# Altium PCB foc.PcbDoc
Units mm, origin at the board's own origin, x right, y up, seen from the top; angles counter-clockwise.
Board outline 89.54 x 51.18 mm, 2 copper layers (Top Layer, Bottom Layer); 143 components, 82 nets, 471 pads, 233 vias.
Unrouted connection lines stored in the file: 246.
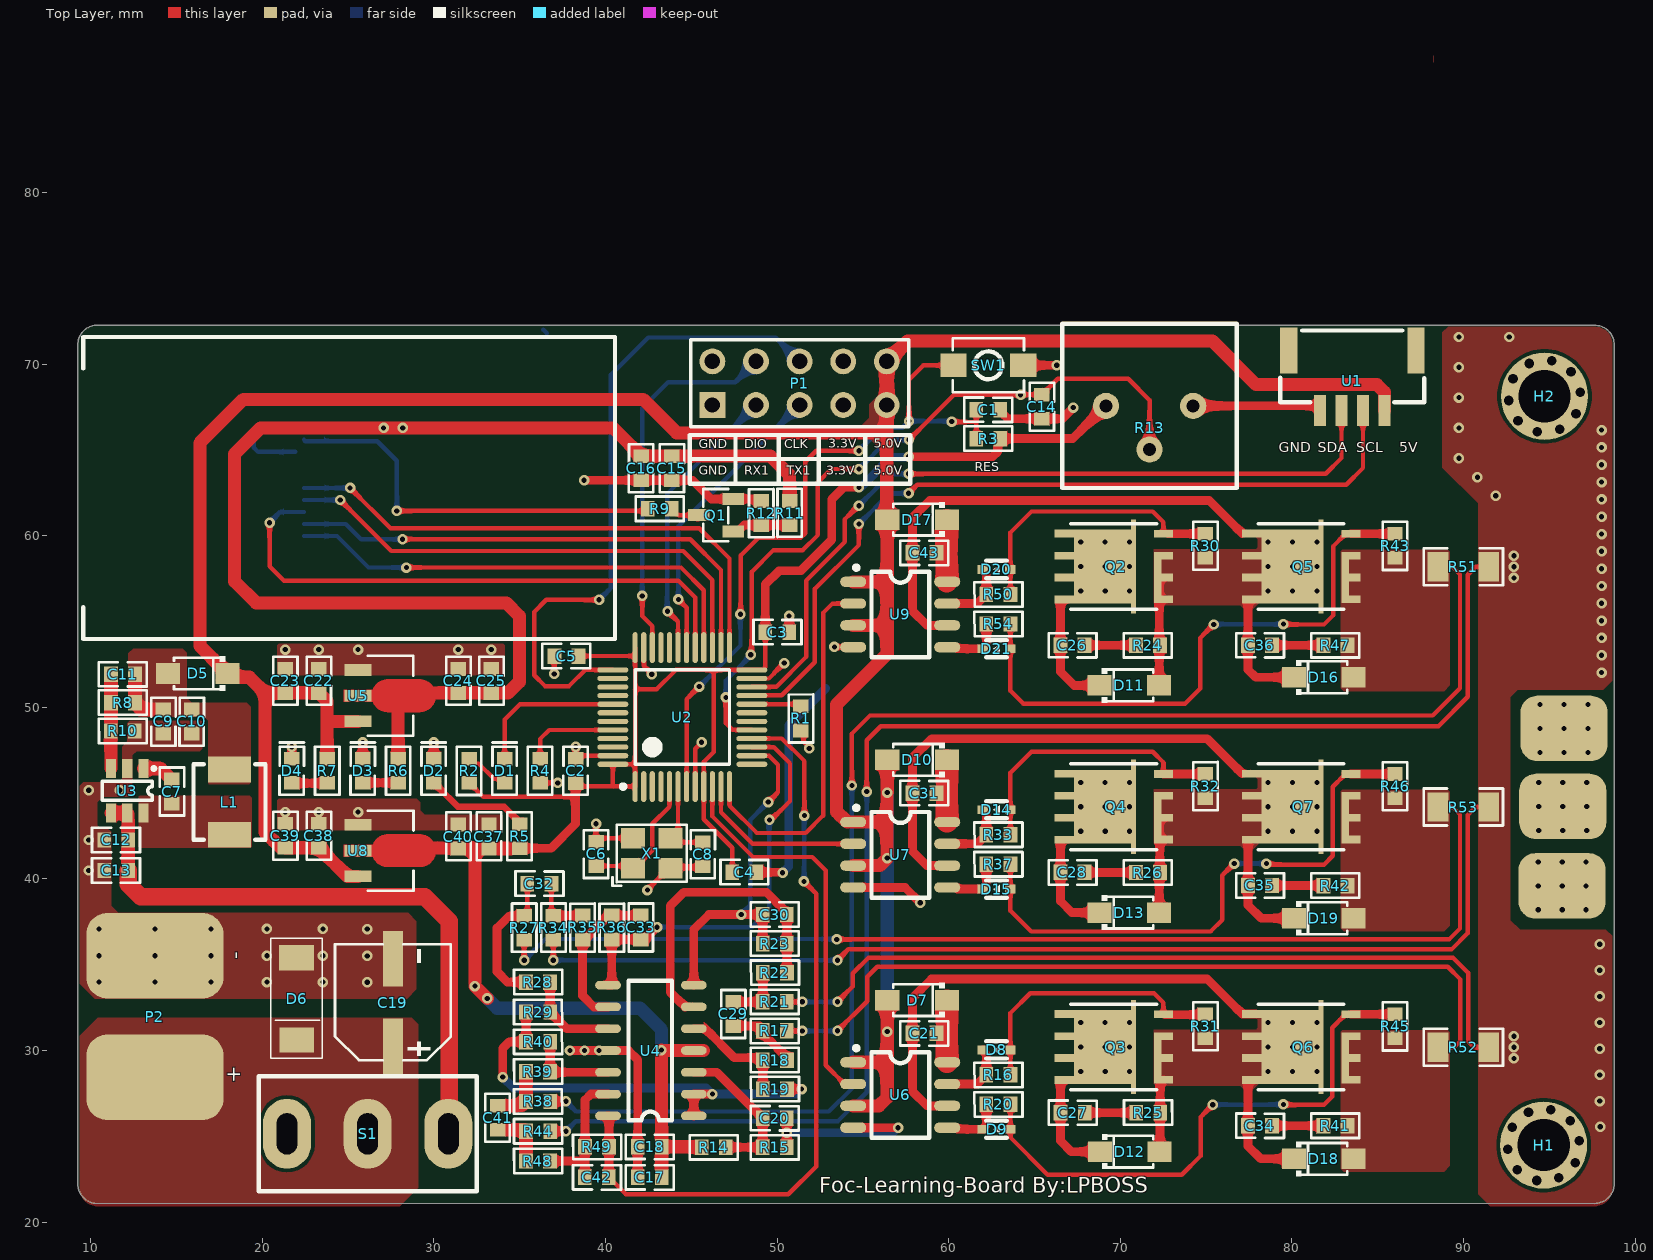
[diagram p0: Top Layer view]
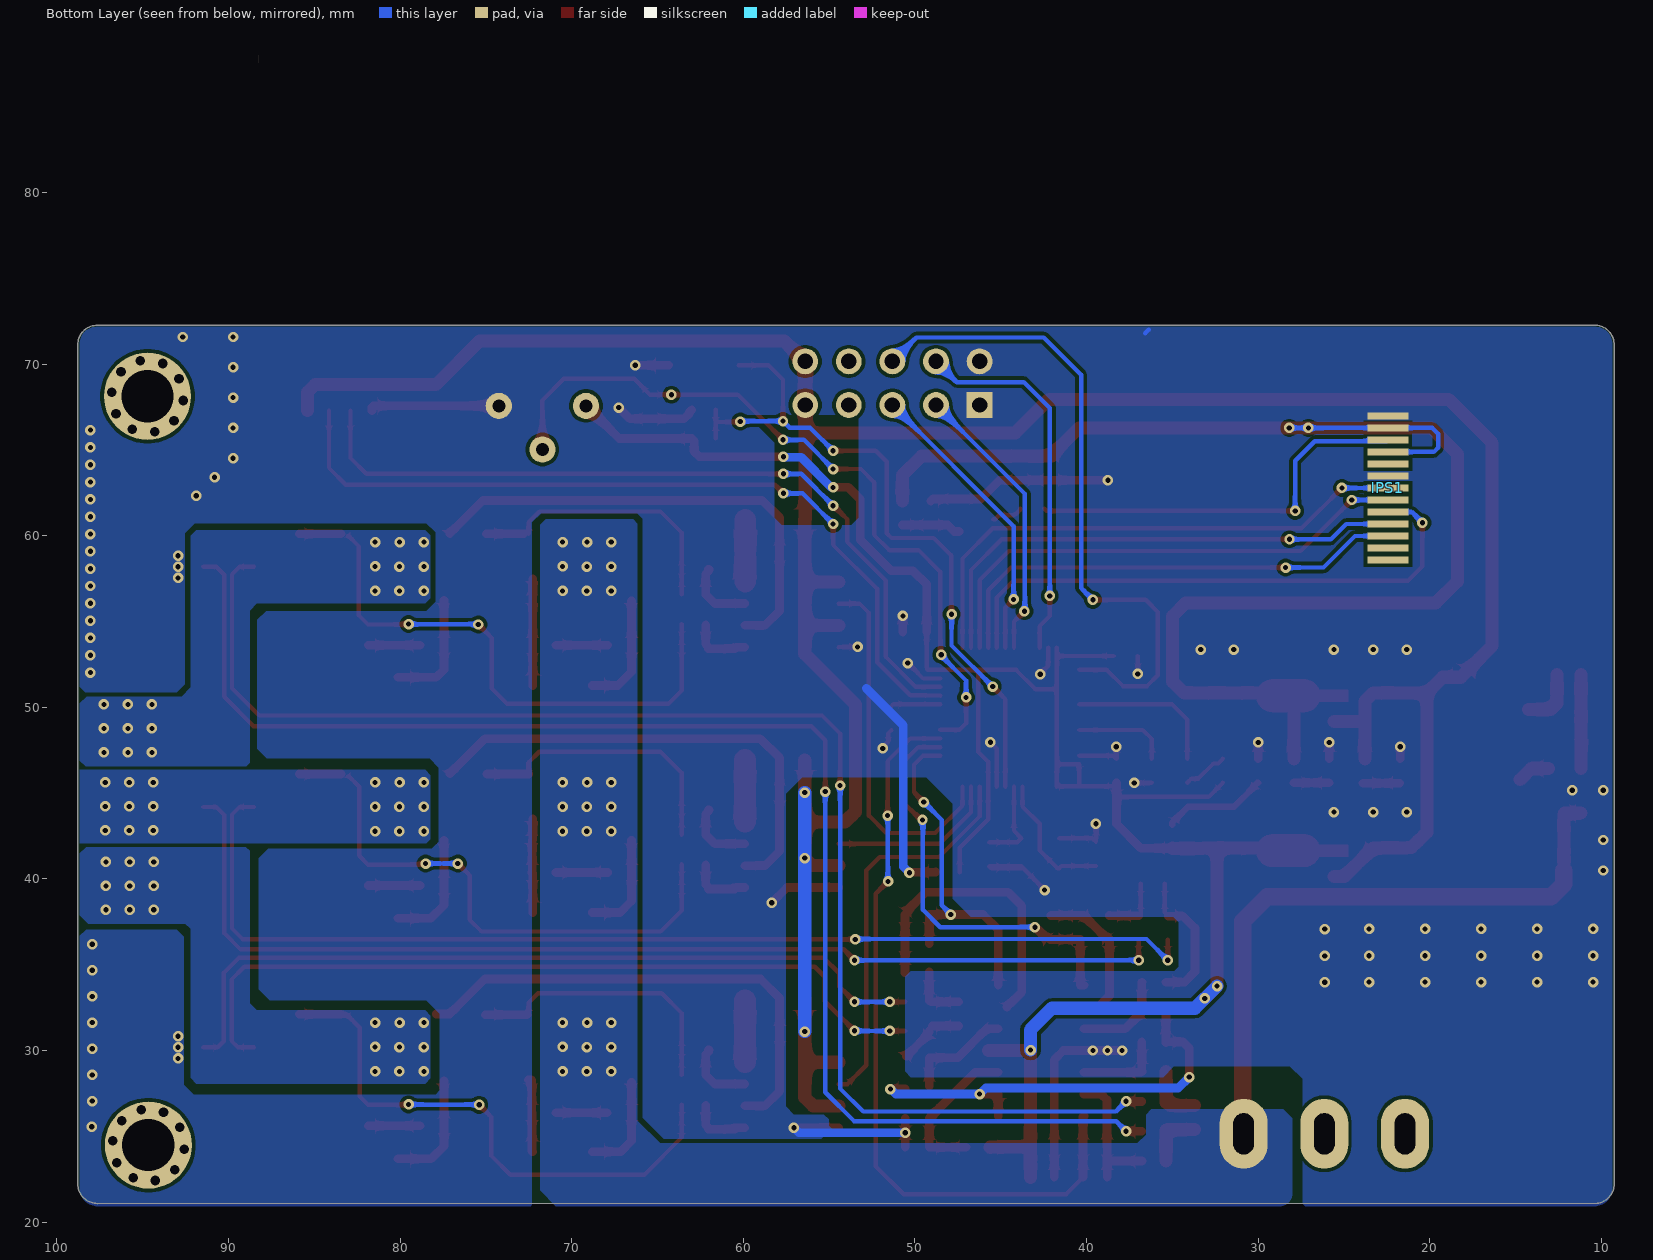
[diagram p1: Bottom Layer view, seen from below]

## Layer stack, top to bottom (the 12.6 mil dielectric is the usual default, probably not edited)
Top Solder: solder mask 0.0102, Solder Resist, Dk 3.5
Top Layer: signal copper 0.0356
Dielectric 1: dielectric 0.32, FR-4, Dk 4.8
Bottom Layer: signal copper 0.0356
Bottom Solder: solder mask 0.0102, Solder Resist, Dk 3.5

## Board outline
10.239,21.092 cw(c10.39,22.226) 9.245,22.226 9.245,22.227 9.245,71.102 9.244,71.12 cw(c10.389,71.12) 10.389,72.265 10.406,72.263 97.635,72.263 97.636,72.263 cw(c97.636,71.119) 98.781,71.12 98.781,71.119 98.781,22.228 98.781,22.226 cw(c97.636,22.226) 97.636,21.082

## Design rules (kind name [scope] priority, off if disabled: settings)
Clearance [All] p1: gap=0.203 ignorepadtopadclearanceinfootprint=TRUE
ComponentClearance [All] p1: gap=0 collisioncheckmode=3 verticalgap=0 showdistances=FALSE
PlaneConnect [All] p1: planeconnectstyle=Direct reliefexpansion=0.508 reliefentries=4 reliefconductorwidth=0.254 reliefairgap=0.254
PolygonConnect [All] p1: connectstyle=Direct reliefconductorwidth=0.254 reliefentries=4 polygonreliefangle="90 Angle" airgapwidth=0.254
RoutingVias [All] p1: holewidth=0.711 width=1.27 viastyle="Through Hole" minholewidth=0.025 minwidth=0.025 maxholewidth=0.711 maxwidth=1.27
SolderMaskExpansion [All] p1: expansion=0.102 istentingtop=FALSE
Width [All] p1: maxlimit=2.54 minlimit=0.025 preferedwidth=0.254
28 further rules are at their usual default settings.

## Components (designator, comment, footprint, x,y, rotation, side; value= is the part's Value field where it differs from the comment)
C1 "104" C0603 62.306,67.335 r0 top
C2 "104" C0603 38.252,46.289 r270 top
C3 "104" C0603 50.013,54.381 r180 top
C4 "104" C0603 48.087,40.395 r180 top
C5 "104" C0603 37.719,52.984 r0 top
C6 "20P" C0603 39.446,41.453 r90 top
C7 "104" C0603 14.732,45.085 r270 top
C8 "20P" C0603 45.665,41.433 r270 top
C9 "22UF" C0603 14.238,49.171 r90 top
C10 "104" C0603 15.889,49.171 r90 top
C11 "220pf" C0603 11.877,51.919 r0 top
C12 "104" C0603 11.481,42.266 r0 top
C13 "22uf" C0603 11.481,40.488 r0 top
C14 "104" C0603 65.43,67.513 r90 top
C15 "10uf" C0603 43.866,63.935 r90 top
C16 "104" C0603 42.078,63.935 r90 top
C17 "10uF" C0603 42.569,22.608 r180 top
C18 "104" C0603 42.569,24.383 r180 top
C19 "470uf" CAP-SMD_BD6.3-L6.6-W6.6-LS7.2-R-RD 27.61,32.791 r270 top
C20 "104" C0603 49.86,26.055 r180 top
C21 "104" C0603 58.582,30.995 r0 top
C22 "10uf" C0603 23.292,51.536 r270 top
C23 "104" C0603 21.336,51.536 r270 top
C24 "10uf" C0603 31.42,51.536 r270 top
C25 "104" C0603 33.351,51.536 r270 top
C26 "104" C0603 67.208,53.614 r180 top
C27 "104" C0603 67.219,26.376 r180 top
C28 "104" C0603 67.208,40.376 r180 top
C29 "104" C0603 47.447,32.131 r90 top
C30 "104" C0603 49.86,37.922 r0 top
C31 "1uf" C0603 58.582,44.995 r0 top
C32 "104" C0603 36.144,39.726 r180 top
C33 "104" C0603 42.062,37.173 r90 top
C34 "104" C0603 78.133,25.614 r180 top
C35 "104" C0603 78.133,39.614 r180 top
C36 "104" C0603 78.133,53.614 r180 top
C37 "104" C0603 33.208,42.468 r270 top
C38 "104" C0603 23.297,42.507 r270 top
C39 "10uf" C0603 21.342,42.507 r270 top
C40 "10uf" C0603 31.425,42.468 r270 top
C41 "104" C0603 33.706,26.086 r90 top
C42 "104" C0603 39.494,22.608 r180 top
C43 "104" C0603 58.582,58.995 r0 top
D1 "LED" LED0603 34.123,46.304 r90 top
D2 "LED" LED0603 29.987,46.304 r90 top
D3 "LED" LED0603 25.852,46.304 r90 top
D4 "LED" LED0603 21.717,46.304 r90 top
D5 "Diode" SOD-123FL_L2.7-W1.8-LS3.8-RD 16.231,51.968 r180 top
D6 "TVS-7.4/12V" SMA 22.996,36.145 r270 top
D7 "Diode" SOD-123FL_L2.7-W1.8-LS3.8-RD 58.152,32.933 r180 top
D8 "Diode" ESC_L1.2-W0.8-LS1.6-RD 62.778,30.029 r0 top
D9 "Diode" ESC_L1.2-W0.8-LS1.6-RD 62.788,25.407 r0 top
D10 "Diode" SOD-123FL_L2.7-W1.8-LS3.8-RD 58.152,46.933 r180 top
D11 "Diode" SOD-123FL_L2.7-W1.8-LS3.8-RD 70.53,51.272 r0 top
D12 "Diode" SOD-123FL_L2.7-W1.8-LS3.8-RD 70.541,24.105 r0 top
D13 "Diode" SOD-123FL_L2.7-W1.8-LS3.8-RD 70.53,38.034 r0 top
D14 "Diode" ESC_L1.2-W0.8-LS1.6-RD 62.778,44.029 r0 top
D15 "Diode" ESC_L1.2-W0.8-LS1.6-RD 62.778,39.407 r0 top
D16 "Diode" SOD-123FL_L2.7-W1.8-LS3.8-RD 81.849,51.745 r0 top
D17 "Diode" SOD-123FL_L2.7-W1.8-LS3.8-RD 58.152,60.933 r180 top
D18 "Diode" SOD-123FL_L2.7-W1.8-LS3.8-RD 81.849,23.683 r0 top
D19 "Diode" SOD-123FL_L2.7-W1.8-LS3.8-RD 81.849,37.704 r0 top
D20 "Diode" ESC_L1.2-W0.8-LS1.6-RD 62.778,58.029 r0 top
D21 "Diode" ESC_L1.2-W0.8-LS1.6-RD 62.778,53.407 r0 top
H1 "Hole" 铜柱孔3 94.666,24.486 r0 top
H2 "Hole" 铜柱孔3 94.717,68.123 r0 top
IPS1 "IPS1.14" IPS 15.661,62.781 r0 top locked
L1 "3.3uH" "0402 TPC 4*4*2" 18.085,44.475 r270 top
P1 "Header 5X2" HDR2X5 46.228,67.615 r0 top
P2 "电源" POWER 13.741,31.979 r90 top
Q1 "44H11" SOT-23-3_L2.9-W1.3-P1.90-LS2.4-BR 46.431,61.19 r0 top
Q2 "N-MOS" TDSON-8 69.609,58.201 r90 top
Q3 "N-MOS" TDSON-8 69.609,30.201 r90 top
Q4 "N-MOS" TDSON-8 69.609,44.201 r90 top
Q5 "N-MOS" TDSON-8 80.534,58.201 r90 top
Q6 "N-MOS" TDSON-8 80.534,30.201 r90 top
Q7 "N-MOS" TDSON-8 80.534,44.201 r90 top
R1 "10K" R0603 51.384,49.352 r90 top
R2 "10K" R0603 32.05,46.296 r90 top
R3 "10K" R0603 62.298,65.659 r180 top
R4 "10K" R0603 36.185,46.296 r270 top
R5 "10K" R0603 34.996,42.483 r90 top
R6 "10K" R0603 27.914,46.296 r270 top
R7 "10K" R0603 23.779,46.296 r270 top
R8 "73.2K" R0603 11.877,50.265 r0 top
R9 "24R" R0603 43.154,61.57 r180 top
R10 "10K" R0603 11.869,48.617 r180 top
R11 "1k" R0603 50.728,61.32 r270 top
R12 "10k" R0603 49.077,61.32 r90 top
R13 "WH160-1-503(B50K)" 滑动变阻器 71.704,66.294 r0 top
R14 "5.1K" R0603 46.304,24.359 r180 top
R15 "5.1K" R0603 49.86,24.359 r180 top
R16 "10" R0603 62.892,28.573 r180 top
R17 "1K" R0603 49.86,31.138 r0 top
R18 "1K" R0603 49.869,29.442 r0 top
R19 "15K" R0603 49.869,27.751 r180 top
R20 "10" R0603 62.892,26.854 r180 top
R21 "1K" R0603 49.86,32.834 r0 top
R22 "1K" R0603 49.869,34.535 r180 top
R23 "15K" R0603 49.86,36.226 r0 top
R24 "10" R0603 71.608,53.608 r0 top
R25 "10" R0603 71.619,26.376 r0 top
R26 "10" R0603 71.608,40.37 r0 top
R27 "1K" R0603 35.259,37.157 r270 top
R28 "1K" R0603 36.062,33.984 r180 top
R29 "15K" R0603 36.071,32.24 r0 top
R30 "10K" R0603 74.957,59.411 r90 top
R31 "10K" R0603 74.957,31.411 r90 top
R32 "10K" R0603 74.957,45.411 r90 top
R33 "10" R0603 62.892,42.573 r180 top
R34 "1K" R0603 36.958,37.157 r270 top
R35 "1K" R0603 38.663,37.166 r90 top
R36 "15K" R0603 40.363,37.166 r90 top
R37 "10" R0603 62.892,40.854 r180 top
R38 "1K" R0603 36.071,27.027 r0 top
R39 "1K" R0603 36.062,28.77 r180 top
R40 "15K" R0603 36.071,30.503 r0 top
R41 "10" R0603 82.533,25.608 r0 top
R42 "10" R0603 82.533,39.608 r0 top
R43 "10K" R0603 86.006,59.406 r90 top
R44 "1K" R0603 36.071,25.29 r0 top
R45 "10K" R0603 86.006,31.406 r90 top
R46 "10K" R0603 86.006,45.406 r90 top
R47 "10" R0603 82.533,53.608 r0 top
R48 "1K" R0603 36.062,23.557 r180 top
R49 "15K" R0603 39.501,24.383 r180 top
R50 "10" R0603 62.892,56.573 r180 top
R51 "20mR" R1206 89.989,58.186 r180 top
R52 "20mR" R1206 89.989,30.186 r180 top
R53 "20mR" R1206 89.989,44.186 r180 top
R54 "10" R0603 62.892,54.854 r180 top
S1 "MTS-10x" SW-TH_HOOYA_SS-12D10G4 26.137,25.146 r180 top
SW1 "Switch" SW-SMD_L4.0-W2.9-LS5.0 62.306,69.926 r180 top
U1 "GH125-4P" CONN-SMD_4P-P1.27_GH125-S04DCA-00 83.515,69.037 r180 top
U2 "STM32F103C8T6" 48P 44.475,49.428 r90 top
U3 "RY8121" SOT-23-6 12.127,45.131 r270 top
U4 "MCP6024" SOP14_L 42.647,29.997 r180 top
U5 "AMS1117" SOT-89_L4.5-W2.5-P1.50-LS4.2-BR 26.932,50.672 r180 top
U6 "EG2104" SOP-8 57.172,27.407 r270 top
U7 "EG2104" SOP-8 57.172,41.407 r270 top
U8 "AMS1117" SOT-89_L4.5-W2.5-P1.50-LS4.2-BR 26.938,41.643 r180 top
U9 "EG2104" SOP-8 57.172,55.407 r270 top
X1 "XTAL-4" OSC-SMD_4P-L3.2-W2.5-BL 42.693,41.498 r0 top

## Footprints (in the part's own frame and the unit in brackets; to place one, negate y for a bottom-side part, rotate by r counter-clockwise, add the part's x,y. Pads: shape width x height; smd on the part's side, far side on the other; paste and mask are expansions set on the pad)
48P [mm] "stm32f103"
  oval 1.8x0.3 smd: 1(-4.05,2.75) 2(-4.05,2.25) 3(-4.05,1.75) 4(-4.05,1.25) 5(-4.05,0.75) 6(-4.05,0.25) 7(-4.05,-0.25) 8(-4.05,-0.75) 9(-4.05,-1.25) 10(-4.05,-1.75) 11(-4.05,-2.25) 12(-4.05,-2.75) 25(4.05,-2.75) 26(4.05,-2.25) 27(4.05,-1.75) 28(4.05,-1.25) 29(4.05,-0.75) 30(4.05,-0.25) 31(4.05,0.25) 32(4.05,0.75) 33(4.05,1.25) 34(4.05,1.75) 35(4.05,2.25) 36(4.05,2.75)
  oval 0.3x1.8 smd: 13(-2.75,-4.05) 14(-2.25,-4.05) 15(-1.75,-4.05) 16(-1.25,-4.05) 17(-0.75,-4.05) 18(-0.25,-4.05) 19(0.25,-4.05) 20(0.75,-4.05) 21(1.25,-4.05) 22(1.75,-4.05) 23(2.25,-4.05) 24(2.75,-4.05) 37(2.75,4.05) 38(2.25,4.05) 39(1.75,4.05) 40(1.25,4.05) 41(0.75,4.05) 42(0.25,4.05) 43(-0.25,4.05) 44(-0.75,4.05) 45(-1.25,4.05) 46(-1.75,4.05) 47(-2.25,4.05) 48(-2.75,4.05)
  silkscreen extent -4.17,-2.75 2.75,3.57
"0402 TPC 4*4*2" [mm] "4.2mm x 4.4mm x 2mm 一体成型功率电感"
  rect 1.5x2.5 smd: 1(-1.9,0) 2(1.9,0)
  silkscreen extent -2.2,-2.1 2.2,2.1
C0603 [mm]
  rect 0.8x0.9 smd mask+0.051: 1(-0.7,0) 2(0.7,0)
  silkscreen extent -1.41,-0.71 1.39,0.72
CAP-SMD_BD6.3-L6.6-W6.6-LS7.2-R-RD [mm]
  rect 3.26x1.15 smd mask+0.051: 1(2.555,0) 2(-2.555,0)
  silkscreen extent -3.39,-3.38 3.36,3.38
CONN-SMD_4P-P1.27_GH125-S04DCA-00 [mm] "P4"
  rect 0.7x1.8 smd mask+0.05: 1(-1.875,1.75) 2(-0.625,1.75) 3(0.625,1.75) 4(1.875,1.75)
  rect 1x2.7 smd mask+0.05: 5(3.705,-1.75) 6(-3.705,-1.75)
  silkscreen extent -4.19,-2.92 4.19,1.27
ESC_L1.2-W0.8-LS1.6-RD [mil]
  rect 23.6x19.7 smd mask+2: 1(-31.5,0) 2(31.5,0)
  silkscreen extent -24,-20 24,20
HDR2X5 [mm] "Connector; Header; 5x2 Position"
  rect 1.5x1.5 hole 0.9: 1(0,0)
  round 1.5 hole 0.9: 2(0,2.54) 3(2.54,0) 4(2.54,2.54) 5(5.08,0) 6(5.08,2.54) 7(7.62,0) 8(7.62,2.54) 9(10.16,0) 10(10.16,2.54)
  silkscreen extent -1.27,-1.27 11.43,3.81
IPS [mm]
  rect 2.4x0.4 smd far side: 1(6.767,-4.2) 2(6.767,-3.5) 3(6.767,-2.8) 4(6.767,-2.1) 5(6.767,-1.4) 6(6.767,-0.7) 7(6.767,0) 8(6.767,0.7) 9(6.767,1.4) 10(6.767,2.1) 11(6.767,2.8) 12(6.767,3.5) 13(6.767,4.2)
  silkscreen extent -6.11,-8.8 24.89,8.8
LED0603 [mm]
  rect 0.8x0.9 smd mask+0.051: A(-0.7,0) N(0.7,0)
  silkscreen extent -1.41,-0.71 1.64,0.72
OSC-SMD_4P-L3.2-W2.5-BL [mm] "贴片晶振"
  rect 1.4x1.2 smd: 1(-1.1,-0.875) 2(1.1,-0.875) 3(1.1,0.875) 4(-1.1,0.875)
  silkscreen extent -2.29,-1.9 2.03,1.65
POWER [mm]
  rrect50% 5x8 smd: 1(-3.541,-0.001) 2(3.541,0.001)
R0603 [mm]
  rect 0.8x0.9 smd mask+0.051: 1(-0.7,0) 2(0.7,0)
  silkscreen extent -1.41,-0.71 1.4,0.72
R1206 [mm]
  rect 1.208x1.701 smd paste-100 mask+0.051: 1(-1.479,0) 2(1.479,0)
  silkscreen extent -2.31,-1.08 2.31,1.08
SMA [mm]
  rect 1.47x2.02 smd: A(0.74,-1.01) N(5.53,-1)
  silkscreen extent -0.4,-2.5 6.6,0.5
SOD-123FL_L2.7-W1.8-LS3.8-RD [mm]
  rect 1.4x1.2 smd: 1(-1.735,0) 2(1.735,0)
  silkscreen extent -1.6,-1 1.38,1
SOP14_L [mm] "8.7*6.2*1.8mm（长宽高）"
  oval 1.5x0.5 smd: 1(-2.5,3.81) 2(-2.5,2.54) 3(-2.5,1.27) 4(-2.5,0) 5(-2.5,-1.27) 6(-2.5,-2.54) 7(-2.5,-3.81) 8(2.5,-3.81) 9(2.5,-2.54) 10(2.5,-1.27) 11(2.5,0) 12(2.5,1.27) 13(2.5,2.54) 14(2.5,3.81)
  silkscreen extent -1.23,-4.06 1.31,4.06
SOP-8 [mm]
  oval 0.6x1.52 smd mask+0.051: 1(-1.905,-2.74) 2(-0.635,-2.74) 3(0.635,-2.74) 4(1.905,-2.74) 5(1.905,2.74) 6(0.635,2.74) 7(-0.635,2.74) 8(-1.905,2.74)
  silkscreen extent -2.85,-2.68 2.5,1.7
SOT-23-3_L2.9-W1.3-P1.90-LS2.4-BR [mm]
  rect 1.25x0.7 smd mask+0.051: 1(1,-0.95) 2(1,0.95) 3(-1,0)
  silkscreen extent -0.73,-1.53 0.73,1.53
SOT-23-6 [mm] "SOT23, 6-Leads, Body 2.90x2.80mm, Pitch 0.95mm, IPC Medium Density"
  rect 1.1x0.6 smd: 1(-1.3,0.95) 2(-1.3,0) 3(-1.3,-0.95) 4(1.3,-0.95) 5(1.3,0) 6(1.3,0.95)
  silkscreen extent -1.37,-1.45 0.55,1.63
SOT-89_L4.5-W2.5-P1.50-LS4.2-BR [mm]
  rect 1.575x0.672 smd paste+0 mask+0.051: 1(1.356,-1.5) 2(1.356,0) 3(1.356,1.5)
  Top Layer region: -2.233,0.95 -0.378,0.95 -0.334,0.949 -0.289,0.946 -0.245,0.94 -0.201,0.933 -0.158,0.924 -0.115,0.912 -0.072,0.899 -0.03,0.884 0.011,0.866 0.051,0.847 0.09,0.826 0.128,0.803 0.166,0.779 0.201,0.752 0.236,0.724 0.269,0.695 0.301,0.664 0.332,0.631 0.36,0.597 0.388,0.562 0.413,0.525 0.437,0.488 0.459,0.449 0.479,0.409 0.491,0.356 2.195,0.356 2.195,-0.356 0.491,-0.356 0.479,-0.41 0.459,-0.449 0.437,-0.488 0.413,-0.526 0.388,-0.562 0.36,-0.598 0.332,-0.631 0.301,-0.664 0.269,-0.695 0.236,-0.725 0.201,-0.753 0.166,-0.779 0.128,-0.804 0.09,-0.827 0.051,-0.848 0.011,-0.867 -0.03,-0.884 -0.072,-0.9 -0.115,-0.913 -0.158,-0.924 -0.201,-0.934 -0.245,-0.941 -0.289,-0.946 -0.334,-0.949 -0.378,-0.95 -2.233,-0.95 -2.277,-0.949 -2.321,-0.946 -2.366,-0.941 -2.41,-0.934 -2.453,-0.924 -2.496,-0.913 -2.539,-0.9 -2.581,-0.884 -2.622,-0.867 -2.662,-0.848 -2.701,-0.827 -2.739,-0.804 -2.776,-0.779 -2.812,-0.753 -2.847,-0.725 -2.88,-0.695 -2.912,-0.664 -2.942,-0.631 -2.971,-0.598 -2.998,-0.562 -3.024,-0.526 -3.048,-0.488 -3.07,-0.449 -3.09,-0.41 -3.108,-0.369 -3.124,-0.327 -3.139,-0.285 -3.151,-0.243 -3.161,-0.199 -3.17,-0.155 -3.176,-0.111 -3.18,-0.067 -3.182,-0.023 -3.182,0.022 -3.18,0.067 -3.176,0.111 -3.17,0.155 -3.161,0.199 -3.151,0.242 -3.139,0.285 -3.124,0.327 -3.108,0.368 -3.09,0.409 -3.07,0.449 -3.048,0.488 -3.024,0.525 -2.998,0.562 -2.971,0.597 -2.942,0.631 -2.912,0.664 -2.88,0.695 -2.847,0.724 -2.812,0.752 -2.776,0.779 -2.739,0.803 -2.701,0.826 -2.662,0.847 -2.622,0.866 -2.581,0.884 -2.539,0.899 -2.496,0.912 -2.453,0.924 -2.41,0.933 -2.366,0.94 -2.321,0.946 -2.277,0.949
  silkscreen extent -1.87,-2.33 0.78,2.33
SW-SMD_L4.0-W2.9-LS5.0 [mm]
  rect 1.53x1.36 smd mask+0.051: 1(-2.035,0) 2(2.035,0)
  silkscreen extent -2.08,-1.58 2.08,1.58
SW-TH_HOOYA_SS-12D10G4 [mil] "拨动开关"
  oval 110x160 hole 47.24 slot 94.49 at 90 deg: 1(-185.04,0) 2(0,0) 3(185.04,0)
  silkscreen extent -250,-132 250,132
TDSON-8 [mm]
  rect 0.45x1.6 smd: 1(-1.925,2.65) 1(-0.635,2.65) 1(0.635,2.65) 1(1.925,2.65)
  rect 5.5x0.3 smd: 1(0,-1.158)
  rect 4.3x3.605 smd: 1(0,0.495)
  rect 0.45x1.1 smd: 2(1.905,-2.9) 3(-1.905,-2.9) 3(-0.635,-2.9) 3(0.635,-2.9)
  rect 2.99x0.45 smd: 3(-0.635,-2.575)
  silkscreen extent -2.5,-2.5 2.5,2.5
滑动变阻器 [mil]
  round 60 hole 30: 1(-100,50) 2(0,-50) 3(100,50)
  silkscreen extent -200,-139 200,239
铜柱孔3 [mil]
  round 23 hole 22: 11(-82.21,-9.67) 11(-72.19,40.5) 11(-60.83,-56.14) 11(-34.6,75.2) 11(-16.21,-81.17) 11(16.21,81.17) 11(34.6,-75.2) 11(60.83,56.14) 11(72.19,-40.5) 11(82.21,9.67)
  round 200 hole 120: 11(0,0)

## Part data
C1 C2 C3 C4 C5 C6 C7 C8 C9 C10 C11 C12 C13 C14 C15 C16 C17 C18 C20 C21 C22 C23 C24 C25 C26 C27 C28 C29 C30 C31 C32 C33 C34 C35 C36 C37 C38 C39 C40 C41 C42 C43: library part C, "无极性电容"
C19: library part CAP+, "电解电容 10uf  贴片型 钽电容的正极是实物有线的一段", BOM_JLCPCB Part Class="Extended Part", BOM_Manufacturer=ROQANG, BOM_Manufacturer Part=RVT1V100M0405
D5 D7 D8 D9 D10 D11 D12 D13 D14 D15 D16 D17 D18 D19 D20 D21: library part 二极管, "Diode 1N series"
H1 H2: "电机的洞"
L1: library part L, "电感"
P1: "Header, 5-Pin, Dual row"
P2: library part power
Q1: library part NPN, "NPN型"
Q2 Q3 Q4 Q5 Q6 Q7: "N沟场效应管"
R1 R2 R3 R4 R5 R6 R7 R8 R9 R10 R11 R12 R14 R15 R16 R17 R18 R19 R20 R21 R22 R23 R24 R25 R26 R27 R28 R29 R30 R31 R32 R33 R34 R35 R36 R37 R38 R39 R40 R41 R42 R43 R44 R45 R46 R47 R48 R49 R50 R51 R52 R53 R54: library part R, "电阻"
R13: "拨码开关", Manufacturer=JML
S1: "MTS10x系列3脚扭子开关"
SW1: "SWITCH"
U3: "18V 2A 1MHz Synchronous Step-Down Regulator"
X1: "贴片晶振"

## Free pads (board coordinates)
  rrect50% 5.08x3.81 smd mask+0.051: 7(95.746,39.591) 7(95.783,44.221) 7(95.86,48.768)

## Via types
v1: diameter 0.61, hole 0.305, Top Layer to Bottom Layer, tented both sides, 233 vias

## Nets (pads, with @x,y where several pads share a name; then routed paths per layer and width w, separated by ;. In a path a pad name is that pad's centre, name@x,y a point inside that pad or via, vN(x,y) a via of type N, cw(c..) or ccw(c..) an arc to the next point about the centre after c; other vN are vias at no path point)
1.65V: R19.1 R29.1 R40.1 U4.1 U4.2 | length 26.1
  Top Layer w0.508: v1(34.011,28.448) 34.011,30.124 34.389,30.503 R40.1 ; R40.1@35.371,30.453 R29.1 ; U4.1 U4.2 v1(46.228,27.457) ; R19.1 v1(51.424,27.751)
  Bottom Layer w0.508: v1(34.011,28.448) 34.646,27.813 45.872,27.813 46.22,27.465 46.22,27.457 51.103,27.457 51.396,27.751 v1(51.424,27.751)
3.3V: C2.2 C3.2 C4.2 C5.2 C17.1 C18.1 C37.2 C40.2 R2.1 R3.1 R5.1 R13.1 R14.2 U2.1 U2.9 U2.24 U2.36 U2.48 U4.4 U8.2 | length 122.5
  Top Layer w0.254: R2.1 32.865,44.78 38.252,44.78 ; C2.2@38.252,45.63 38.492,45.39 40.488,45.39 ; C5.2 U2.36@41.725,52.984 ; U2.1 U2.1@41.725,45.39 ; U2.36 U2.36@41.725,52.984 ; C4.2 47.387,41.818 45.725,43.479 U2.9 45.725,46.818 46.304,47.396 46.304,52.178 ; C3.2 49.313,52.35 49.284,52.322 49.284,52.2 49.263,52.178 46.304,52.178 ; 40.488,45.39 40.425,45.452 U2.48 41.725,46.678 ; 40.488,45.39 U2.1@41.725,45.39 ; U2.1@41.725,45.39 41.725,46.678 ; 41.725,46.678 41.725,51.054 ; 41.725,51.054 U2.36@41.725,52.984 ; 41.725,51.054 42.977,51.054 44.101,52.178 46.304,52.178
  Top Layer w0.508: R5.1 36.83,41.783 38.252,43.205 38.252,44.78 38.252,45.39 C2.2 ; C3.2 49.313,57.161 50.114,57.963 51.384,57.963 53.188,59.766 53.188,62.128 53.873,62.814 v1(54.762,62.814) ; v1(57.658,64.601) 62.554,64.601 62.852,64.898 62.852,65.513 R3.1 63.195,65.659 67.229,65.659 69.134,67.564 R13.1
  Top Layer w0.762: 28.88,41.783 28.904,41.807 31.425,41.807 32.391,41.807 ; v1(33.112,33.03) v1(32.391,33.751) 32.391,41.807 ; C37.2@33.185,41.807 32.391,41.807 ; C37.2 34.981,41.768 R5.1 ; v1(43.256,30.023) v1@43.269,30.01 ; C17.1 C18.1 ; R14.2 45.579,24.383 C18.1 ; U4.4@45.695,29.997 43.282,29.997 v1@43.269,30.01 ; C18.1 v1@43.269,30.01
  Bottom Layer w0.508: v1(54.762,62.814) 54.782,62.834 54.895,62.834 56.629,64.567 57.552,64.567 57.567,64.581 57.644,64.581 v1@57.658,64.567
  Bottom Layer w0.762: v1(32.391,33.751) 33.68,32.461 42.012,32.461 43.269,31.204 43.269,30.036 v1(43.256,30.023)
3.3V_ips: C15.2 C16.2 C24.2 C25.2 IPS1.10 IPS1.12 R6.1 R11.1 U5.2 | length 86.8
  Top Layer w0.762: R6.1 27.914,50.317 28.219,50.622 ; 28.778,50.648 28.967,50.836 C24.2 C25.2 34.326,50.836 34.976,51.486 34.976,55.321 34.214,56.083 19.634,56.083 18.39,57.328 18.39,64.77 19.9,66.281 v1(27.064,66.281) v1(28.182,66.281) 40.433,66.281 42.009,64.704 42.009,64.654 42.028,64.635 C15.2 49.614,64.635 50.728,63.521 R11.1
  Bottom Layer w0.254: IPS1.10@21.92,64.881 19.752,64.881 19.507,65.126 19.507,65.938 19.849,66.281 IPS1.12 v1(27.064,66.281) v1(28.182,66.281)
5V: C22.2 C23.2 C38.2 C39.2 D5.1 D7.2 D10.2 D17.2 P1.9 P1.10 R7.1 U1.1 U5.3 U6.1 U6.3 U7.1 U7.3 U8.3 U9.1 U9.3 | length 180.4
  Top Layer w0.762: R7.1 23.779,49.154 ; 23.798,49.172 23.779,49.154 ; 23.825,49.172 U5.3 ; U8.3 24.961,40.143 C38.2 C39.2 21.323,41.826 21.07,41.826 20.673,42.223 20.65,42.223 20.165,42.707 20.165,50.825 ; U6.3 55.931,26.772 56.417,27.258 56.417,29.312 ; U6.1 56.417,29.312 ; U7.3 55.978,40.772 v1@56.415,41.209 ; U9.3 56.417,54.772 ; U9.1 56.417,57.312 ; D17.2@56.388,60.962 56.388,65.989 ; v1(56.413,41.211) 56.413,43.312 ; v1(56.413,45.026) 56.413,43.312 ; D7.2@56.417,33.029 D7.2 v1(56.417,31.1) 56.417,29.312 ; v1@56.417,45.026 D10.2 ; D17.2 56.417,57.312 ; U1.1 85.39,68.362 84.944,68.809 77.902,68.809 75.362,71.349 57.61,71.349 56.416,70.155 P1.10 P1.9 56.388,65.989 ; 20.165,50.825 22.035,50.825 22.046,50.836 C22.2 23.779,50.349 23.779,49.154 ; 20.165,50.825 19.241,51.749 18.185,51.749 16.358,53.576 16.358,65.405 18.898,67.945 42.189,67.945 44.145,65.989 56.388,65.989 ; 56.413,43.312 U7.1 54.066,43.312 53.467,43.91 53.467,50.165 56.417,53.115 56.417,54.772 ; 56.417,54.772 56.417,57.312
  Bottom Layer w0.762: v1(56.417,31.1) 56.417,32.933 v1@56.417,45.026
12V: C12.2 C13.2 C26.2 C27.2 C28.2 D11.1 D12.1 D13.1 Q2.1 Q3.1 Q4.1 S1.1 U3.4 U3.5 | length 55.9
  Top Layer w0.508: Q3.1@66.508,28.154 66.508,26.386 C27.2 66.508,26.365 66.508,24.741 67.145,24.105 D12.1 ; Q4.1@66.508,42.247 C28.2 66.508,38.711 67.185,38.034 D13.1 ; Q2.1@66.508,56.195 C26.2 66.508,52.072 67.307,51.272 D11.1
  Top Layer w0.762: U3.4 U3.5 ; C13.2 C12.2 U3.5@12.181,43.778
  Top Layer w1.016: C13.2 12.181,39.686 12.903,38.964 29.464,38.964 30.886,37.541 30.886,25.196 S1.1
  other v1: 67.686,28.778 69.113,28.778 70.531,28.778 67.686,30.196 69.109,30.201 70.531,30.205 67.686,31.623 69.104,31.623 70.531,31.623 67.686,42.778 69.113,42.778 70.531,42.778 67.686,44.196 69.109,44.201 70.531,44.205 67.686,45.623 69.104,45.623 70.531,45.623 67.686,56.778 69.113,56.778 70.531,56.778 67.686,58.196 69.109,58.201 70.531,58.205 67.686,59.623 69.104,59.623 70.531,59.623
A: C21.1 C34.2 D12.2 D18.1 pad.7@95.746,39.591 Q3.3 Q6.1 R25.2 R31.1 U6.6 | length 40.3
  Top Layer w0.508: U6.6 58.737,26.772 57.882,27.627 C21.1 57.882,33.049 58.996,34.163 75.069,34.163 77.107,32.126 Q6.1@77.884,32.126 ; D12.2 72.308,24.137 72.308,26.365 R25.2 72.319,28.267 72.348,28.296 Q3.3@72.509,28.296 ; Q6.1@77.433,28.23 77.433,24.433 78.183,23.683 D18.1
  other v1: 78.611,28.778 80.038,28.778 81.456,28.778 78.611,30.196 80.034,30.201 81.456,30.205 78.611,31.623 80.029,31.623 81.456,31.623 94.349,38.194 95.746,38.194 97.143,38.194 94.349,39.591 95.746,39.591 97.143,39.591 94.349,40.988 95.746,40.988 97.143,40.988
B: C31.1 C35.2 D13.2 D19.1 pad.7@95.783,44.221 Q4.3 Q7.1 R26.2 R32.1 U7.6 | length 40.6
  Top Layer w0.508: U7.6 58.737,40.772 57.882,41.627 C31.1 57.882,47.049 59.006,48.173 75.059,48.173 Q7.1@77.107,46.126 ; D13.2 72.265,40.327 R26.2 72.294,40.384 72.294,42.267 72.265,42.296 Q4.3@72.265,43.484 ; Q7.1@77.433,42.23 C35.2 77.433,38.48 78.209,37.704 D19.1
  other v1: 78.611,42.778 80.038,42.778 81.456,42.778 94.386,42.824 95.783,42.824 97.18,42.824 78.611,44.196 80.034,44.201 81.456,44.205 94.386,44.221 95.783,44.221 97.18,44.221 78.611,45.623 80.029,45.623 81.456,45.623 94.386,45.618 95.783,45.618 97.18,45.618
BOOT0: R4.1 U2.44 | length 5.6
  Top Layer w0.254: R4.1 36.185,48.148 36.715,48.678 U2.44
BOOT1: R1.2 U2.20 | length 2.9
  Top Layer w0.254: U2.20 51.258,50.178 R1.2
C: C36.2 C43.1 D11.2 D16.1 pad.7@95.86,48.768 Q2.3 Q5.1 R24.2 R30.1 U9.6 | length 41.4
  Top Layer w0.508: U9.6 58.737,54.772 57.882,55.627 C43.1 57.882,61.049 58.885,62.052 75.18,62.052 Q5.1@77.107,60.126 ; D11.2 Q2.3@72.265,57.484 ; Q5.1@77.433,56.23 77.433,52.196 77.883,51.745 D16.1
  other v1: 94.463,47.371 95.86,47.371 97.257,47.371 94.463,48.768 95.86,48.768 97.257,48.768 94.463,50.165 95.86,50.165 97.257,50.165 78.611,56.778 80.038,56.778 81.456,56.778 78.611,58.196 80.034,58.201 81.456,58.205 78.611,59.623 80.029,59.623 81.456,59.623
DC: IPS1.5 U2.29 | length 33.3
  Top Layer w0.254: v1(20.422,60.757) 20.422,58.217 21.26,57.379 44.247,57.379 45.225,56.4 U2.29
  Bottom Layer w0.254: v1(20.422,60.757) 21.045,61.381 IPS1.5
GND: C1.2 C2.1 C3.1 C4.1 C5.1 C6.2 C8.2 C9.1 C10.1 C12.1 C13.1 C14.1 C15.1 C16.1 C17.2 C18.2 C19.2 C20.1 C22.1 C23.1 C24.1 C25.1 C37.1 C38.1 C39.1 C40.1 D2.N D3.N D4.N D6.A IPS1.8 IPS1.13 P1.1 P1.2 P2.2 Q1.2 R1.1 R4.2 R10.1 R12.2 R13.3 R15.1 R21.2 R34.2 R44.2 R51.1 R52.1 R53.1 SW1.1 U1.4 U2.8 U2.23 U2.35 U2.47 U3.2 U4.11 U5.1 U6.4 U7.4 U8.1 U9.4 X1.2 X1.4 | length 286.6
  Top Layer w0.254: R4.2 36.188,45.593 v1(37.211,45.593) ; v1(36.957,35.255) R34.2 ; v1(37.008,51.943) 37.008,52.973 C5.1 ; C2.1 C2.1@38.258,46.994 ; v1(38.258,47.694) C2.1@38.258,46.994 ; v1(39.446,43.205) C6.2 39.666,42.373 X1.4 ; U2.47 38.442,47.178 C2.1@38.258,46.994 ; U2.35 42.234,53.47 42.234,52.424 42.697,51.961 v1(42.697,51.918) ; v1(42.443,39.345) 42.443,39.373 43.803,40.733 C8.2 45.556,40.623 X1.2 ; U2.8 45.225,47.588 v1(45.593,47.955) ; U2.23 49.519,51.678 v1(50.419,52.578) ; R21.2 v1(51.46,32.834) ; R1.1 51.543,48.494 51.543,48.02 51.867,47.696 v1(51.867,47.6) ; v1(53.34,53.518) 53.348,53.51 54.424,53.51 U9.4 ; v1(53.518,32.842) 54.407,33.731 54.407,34.493 55.321,35.408 89.383,35.408 90.272,34.519 90.272,30.531 90.617,30.186 R52.1 ; v1(53.518,35.264) 54.144,35.89 55.605,35.89 89.298,35.89 90.248,36.84 90.248,43.724 90.71,44.186 R53.1 ; v1(55.22,45.085) 55.22,48.082 56.032,48.895 88.536,48.895 90.248,50.607 90.248,57.724 90.71,58.186 R51.1
  Top Layer w0.508: D4.N v1(21.717,47.694) ; D3.N v1(25.852,47.948) ; D2.N v1(29.988,47.948) ; R44.2 37.685,25.29 v1(37.694,25.298) ; v1(36.957,35.255) v1(36.957,35.255) ; v1@37.922,29.972 37.95,29.972 37.975,29.997 41.337,29.997 41.869,29.465 C18.2 C17.2 ; v1(38.749,63.235) C16.1 45.071,63.235 46.165,62.14 48.956,62.14 R12.2 ; C4.1 48.804,40.378 50.3,40.378 v1(50.317,40.361) ; R15.1 v1(50.56,25.207) C20.1 ; v1(50.698,55.321) 50.706,55.314 50.706,54.389 C3.1 ; U6.4 v1(57.048,25.502) ; U7.4 57.45,39.502 v1(58.344,38.608) ; C1.2 63.152,67.189 63.152,67.111 63.45,66.813 C14.1 66.61,66.813 v1(67.259,67.462) ; SW1.1 v1(66.294,69.926) ; R13.3 81.544,67.564 81.64,67.468 U1.4
  Bottom Layer w0.254: 36.373,72.009 36.576,71.806 ; v1(36.957,35.255) v1@53.518,35.255 ; v1(37.694,25.298) 38.278,25.883 53.543,25.883 55.22,27.559 v1(55.22,45.085) ; v1(51.46,32.834) v1@53.518,32.834
  Bottom Layer w0.508: v1(50.317,40.361) 50.673,40.716 50.673,48.946 52.831,51.104 ; v1(50.56,25.207) 56.753,25.207 v1(57.048,25.502)
  other v1: 97.968,25.552 97.942,27.051 97.942,28.575 92.939,29.538 37.922,29.997 38.773,29.997 39.624,29.997 97.942,30.099 92.939,30.186 92.939,30.833 97.942,31.623 97.942,33.147 10.476,33.985 13.74,33.985 17.004,33.985 20.269,33.985 23.533,33.985 26.111,33.975 97.942,34.671 10.476,35.519 13.74,35.519 17.004,35.519 20.269,35.519 23.533,35.519 26.111,35.509 97.942,36.195 10.476,37.084 13.74,37.084 17.004,37.084 20.269,37.084 23.533,37.084 26.111,37.074 9.881,40.488 9.881,42.266 21.336,43.891 23.292,43.891 25.581,43.891 9.881,45.161 11.684,45.161 98.044,52.019 98.044,53.029 21.331,53.365 23.287,53.365 25.576,53.365 31.415,53.365 33.345,53.365 98.044,54.038 98.044,55.048 98.044,56.057 98.044,57.067 92.939,57.538 98.044,58.076 92.939,58.186 92.939,58.833 98.044,59.085 98.044,60.095 98.044,61.104 98.044,62.114 91.882,62.321 98.044,63.123 90.805,63.398 98.044,64.133 89.728,64.516 98.044,65.142 98.044,66.152 89.728,66.281 89.728,68.047 89.728,69.812 89.728,71.577 92.669,71.577
HO_A: D8.2 Q3.2 R16.1 R31.2 | length 16.4
  Top Layer w0.254: R16.1 63.592,30.029 63.592,32.181 64.747,33.335 71.96,33.335 72.509,32.787 Q3.2
  Top Layer w0.508: Q3.2@72.585,32.085 R31.2@75.028,32.085
HO_B: D14.2 Q4.2 R32.2 R33.1 | length 16.4
  Top Layer w0.254: R33.1 63.592,46.181 64.823,47.411 71.884,47.411 72.509,46.787 Q4.2 ; R32.2@74.952,46.106 R32.2
  Top Layer w0.508: Q4.2 R32.2@74.952,46.106
HO_C: D20.2 Q2.2 R30.2 R50.1 | length 16.1
  Top Layer w0.254: R50.1 63.592,58.029 63.592,60.181 64.823,61.411 71.884,61.411 72.509,60.787 Q2.2
  Top Layer w0.508: Q2.2@72.805,60.111 R30.2
IA+: D18.2 Q6.3 R17.2 R41.2 R45.1 R52.2 | length 47
  Top Layer w0.254: R17.2 v1(51.46,31.138) ; v1(53.518,31.146) 55.245,32.873 55.245,34.29 55.829,34.874 89.078,34.874 89.814,34.138 89.814,30.556 89.444,30.186 R52.2
  Bottom Layer w0.254: v1(51.46,31.138) v1@53.518,31.138
IB+: D19.2 Q7.3 R27.2 R42.2 R46.1 R53.2 | length 64.6
  Top Layer w0.254: v1(35.257,35.255) v1(35.257,35.255) R27.2 ; v1(53.467,36.474) 89.159,36.474 89.791,37.106 89.791,43.749 89.355,44.186 R53.2
  Bottom Layer w0.254: v1(35.257,35.255) 36.502,36.5 53.442,36.5 v1(53.467,36.474)
IC+: D16.2 Q5.3 R38.2 R43.1 R47.2 R51.2 | length 83.7
  Top Layer w0.254: v1(54.356,45.441) 54.356,48.463 55.412,49.52 88.205,49.52 89.791,51.106 89.791,57.749 89.355,58.186 R51.2
  Top Layer w0.508: R38.2 37.685,27.027 v1(37.694,27.036)
  Bottom Layer w0.254: v1(37.694,27.036) 38.288,26.441 53.01,26.441 54.356,27.788 v1(54.356,45.441)
INA+: C20.2 R14.1 R15.2 U4.3 | length 9
  Top Layer w0.508: U4.3 46.488,28.727 C20.2 R15.2 R14.1
INB+: R18.1 R19.2 U4.5 | length 6.4
  Top Layer w0.508: U4.5 45.822,31.267 47.507,29.582 49.169,29.582 R19.2@49.169,27.92
INB-: C30.2 R22.1 R23.2 U4.6 | length 17.1
  Top Layer w0.508: U4.6@44.651,32.537 44.628,32.537 43.764,33.401 43.764,38.43 44.552,39.218 49.378,39.218 C30.2@50.444,38.151 ; C30.2 50.569,37.914 R22.1
INC+: R28.1 R29.2 U4.10 | length 5.6
  Top Layer w0.508: R28.1 36.771,33.975 36.771,32.19 36.917,32.044 36.967,32.044 37.744,31.267 U4.10
INC-: C33.2 R35.1 R36.2 U4.9 | length 9
  Top Layer w0.508: R35.1 38.663,33.193 39.319,32.537 U4.9 ; R35.1@38.711,36.418 40.16,37.866 R36.2 42.055,37.866 C33.2 ; C33.2@42.055,37.853 C33.2@42.062,37.86
IND+: R39.1 R40.2 U4.12 | length 5.1
  Top Layer w0.508: R40.2 36.771,28.779 R39.1 36.805,28.727 U4.12
IND-: C42.2 R48.1 R49.2 U4.13 | length 8.1
  Top Layer w0.254: 38.728,23.557 38.794,23.492
  Top Layer w0.508: R48.1 38.728,23.557 ; C42.2 38.794,23.492 38.794,24.376 R49.2 38.8,27.116 39.141,27.457 U4.13
LED_PWM: D1.N U2.41 | length 9
  Top Layer w0.254: D1.N 34.123,49.286 35.015,50.178 U2.41
LO_A: D9.2 Q6.2 R20.1 R45.2 | length 32.7
  Top Layer w0.254: R20.1 63.592,25.407 63.594,25.405 63.594,24.925 65.761,22.758 73.584,22.758 74.678,23.853 74.678,26.122 v1(75.389,26.833) ; v1(79.504,26.858) 79.529,26.833 81.866,26.833 82.349,27.315 82.349,31.329 83.011,31.991 83.011,32.008 83.109,32.106 Q6.2
  Top Layer w0.508: Q6.2 R45.2@85.882,32.106
  Bottom Layer w0.254: v1(75.389,26.833) 75.402,26.845 79.491,26.845 v1(79.504,26.858)
LO_B: D15.2 Q7.2 R37.1 R46.2 | length 32.8
  Top Layer w0.254: R37.1 63.592,39.407 63.592,38.147 64.808,36.932 75.26,36.932 75.946,37.617 75.946,40.208 v1(76.632,40.894) ; v1(78.511,40.894) 78.577,40.828 81.866,40.828 82.384,41.346 82.384,45.363 Q7.2@83.011,45.991
  Top Layer w0.508: Q7.2 R46.2@85.882,46.106
  Bottom Layer w0.254: v1(76.632,40.894) v1(78.511,40.894)
LO_C: D21.2 Q5.2 R43.2 R54.1 | length 34.2
  Top Layer w0.254: R54.1 63.592,53.407 63.592,50.958 64.349,50.201 73.764,50.201 74.653,51.09 74.653,54.036 v1(75.44,54.824) ; v1(79.504,54.849) 79.529,54.824 81.866,54.824 82.396,55.354 82.396,59.376 Q5.2@83.011,59.991
  Top Layer w0.508: Q5.2 R43.2@85.882,60.106
  Bottom Layer w0.254: v1(75.44,54.824) 75.453,54.836 79.491,54.836 v1(79.504,54.849)
NetC7_1: C7.1 U3.1 | length 1.9
  Top Layer w0.762: U3.1 14.086,46.431 C7.1
NetC7_2: C7.2 L1.2 U3.6
NetC9_2: C9.2 C10.2 C11.2 D5.2 L1.1 R8.2 | length 3.5
  Top Layer w0.762: R8.2@12.577,50.215 C11.2 ; R8.2@12.596,50.196 12.922,49.871 C9.2
NetC11_1: C11.1 R8.1 R10.2 U3.3 | length 5.5
  Top Layer w0.762: U3.3 11.173,46.435 11.173,48.613 R10.2 11.173,48.621 11.173,50.261 R8.1 11.177,50.293 C11.1
NetC14_2: C14.2 R13.2 U2.17 | length 44.1
  Top Layer w0.254: v1(47.015,50.571) 47.015,49.073 47.401,48.687 48.517,48.687 U2.17 ; v1(48.463,53.061) 48.514,53.111 48.514,57.887 49.784,59.157 51.486,59.157 52.375,60.046 52.375,63.119 53.137,63.881 v1(54.762,63.881) ; v1(57.683,65.583) 60.314,68.213 v1(64.186,68.213) C14.2 66.356,69.139 70.46,69.139 71.704,67.894 R13.2
  Bottom Layer w0.254: v1(47.015,50.571) 47.015,51.558 48.463,53.006 v1(48.463,53.061) ; v1(54.762,63.881) 56.464,65.583 v1(57.683,65.583)
NetC19_1: C19.1 D6.N P2.1 S1.2
NetC21_2: C21.2 D7.1 U6.8 | length 3.6
  Top Layer w1.27: U6.8@59.899,29.324 D7.1@59.899,32.92
NetC26_1: C26.1 R24.1 | length 3
  Top Layer w0.508: C26.1 70.903,53.614 R24.1
NetC27_1: C27.1 R25.1 | length 3
  Top Layer w0.508: C27.1 R25.1
NetC28_1: C28.1 R26.1 | length 3
  Top Layer w0.508: C28.1 70.903,40.376 R26.1
NetC29_1: C29.1 R17.1 R18.2 | length 3.5
  Top Layer w0.508: C29.1 R17.1@48.979,31.431 ; R17.1 49.16,31.088 R17.1@49.306,30.942 ; R17.1@49.289,30.874 R18.2@50.483,29.68
NetC29_2: C29.2 R21.1 R22.2 | length 3.4
  Top Layer w0.508: C29.2 49.08,32.831 49.16,32.911 49.169,32.92 R22.2@49.169,34.568
NetC31_2: C31.2 D10.1 U7.8 | length 3.6
  Top Layer w1.27: U7.8@59.899,43.324 D10.1@59.899,46.92
NetC32_1: C32.1 R34.1 R35.2 | length 3.6
  Top Layer w0.254: C32.1 36.844,37.971 R34.1
  Top Layer w0.508: R34.1 38.655,37.858 R35.2
NetC32_2: C32.2 R27.1 R28.2 | length 8.3
  Top Layer w0.254: R27.1@35.229,37.828 R27.1 35.444,38.043 C32.2
  Top Layer w0.508: R27.1@35.229,37.828 34.376,37.828 33.68,37.132 33.68,34.595 34.292,33.984 R28.2
NetC34_1: C34.1 R41.1 | length 3
  Top Layer w0.508: C34.1 81.827,25.614 R41.1
NetC35_1: C35.1 R42.1 | length 3
  Top Layer w0.508: C35.1 81.827,39.614 R42.1
NetC36_1: C36.1 R47.1 | length 3
  Top Layer w0.508: C36.1 81.827,53.614 R47.1
NetC41_1: C41.1 R44.1 R48.2 | length 3.5
  Top Layer w0.762: C41.1 35.275,25.386 35.302,25.359 35.352,25.359 35.371,25.34 R44.1 35.371,23.566 R48.2
NetC41_2: C41.2 R38.1 R39.2 | length 3.5
  Top Layer w0.762: C41.2 35.129,26.786 35.302,26.958 35.352,26.958 35.371,26.977 R38.1 35.362,27.036 R39.2
NetC43_2: C43.2 D17.1 U9.8 | length 3.6
  Top Layer w0.254: U9.8@59.887,57.337 U9.8
  Top Layer w1.27: U9.8@59.887,57.337 D17.1
NetD1_A: D1.A R2.2 | length 2.6
  Top Layer w0.254: R2.2 32.323,46.723 32.601,46.723 33.481,45.843 33.883,45.843 D1.A
NetD2_A: D2.A R5.2 | length 6.1
  Top Layer w0.381: D2.A 30.037,45.604 30.247,45.395 30.247,45.345 31.396,44.196 34.087,44.196 35.001,43.282 R5.2@35.001,43.155
NetD3_A: D3.A R6.2 | length 2.1
  Top Layer w0.254: R6.2@27.906,45.604 R6.2
  Top Layer w0.508: D3.A R6.2@27.906,45.604
NetD4_A: D4.A R7.2 | length 2.2
  Top Layer w0.254: D4.A D4.A@21.754,45.568
  Top Layer w0.508: D4.A@21.754,45.568 R7.2@23.901,45.568
NetD8_1: D8.1 R16.2 U6.7 | length 4
  Top Layer w0.508: U6.7 61.661,28.042 R16.2 ; D8.1 62.02,30.029 62.024,30.025 62.024,29.933 62.192,29.765 R16.2@62.192,28.623
NetD9_1: D9.1 R20.2 U6.5 | length 3.5
  Top Layer w0.508: U6.5 60.397,25.502 60.491,25.407 D9.1@61.932,25.407 ; D9.1@62.024,25.411 62.024,25.502 62.192,25.671 R20.2@62.192,26.804
NetD14_1: D14.1 R33.2 U7.7 | length 4
  Top Layer w0.508: U7.7 61.661,42.042 R33.2 ; D14.1 62.02,44.029 62.024,44.025 62.024,43.933 62.192,43.765 R33.2@62.192,42.623
NetD15_1: D15.1 R37.2 U7.5 | length 3.5
  Top Layer w0.508: U7.5 60.397,39.502 60.491,39.407 D15.1@61.932,39.407 ; D15.1@62.024,39.411 62.024,39.502 62.192,39.671 R37.2@62.192,40.804
NetD20_1: D20.1 R50.2 U9.7 | length 4
  Top Layer w0.508: U9.7 61.661,56.042 R50.2 ; D20.1 62.02,58.029 62.024,58.025 62.024,57.933 62.192,57.765 R50.2@62.192,56.623
NetD21_1: D21.1 R54.2 U9.5 | length 3.5
  Top Layer w0.508: U9.5 60.397,53.502 60.491,53.407 D21.1@61.932,53.407 ; D21.1@62.024,53.411 62.024,53.502 62.192,53.671 R54.2@62.192,54.804
NetIPS1_11: IPS1.11 R9.2 | length 23.5
  Top Layer w0.254: v1(27.838,61.443) 42.327,61.443 R9.2
  Bottom Layer w0.254: IPS1.11 22.501,65.508 26.694,65.508 27.838,64.364 v1(27.838,61.443)
NetQ1_1: Q1.1 R11.2 R12.1 | length 3.5
  Top Layer w0.508: Q1.1 47.706,60.24 48.085,60.62 R12.1 ; R12.1@49.027,60.62 R11.2
NetQ1_3: Q1.3 R9.1 | length 1.9
  Top Layer w0.254: R9.1 43.854,61.52 44.127,61.247 44.212,61.247 44.275,61.183 45.092,61.183 45.315,60.96 Q1.3@45.431,60.96
OSCIN: C6.1 U2.5 X1.1 | length 7.9
  Top Layer w0.254: C6.1 41.464,40.753 X1.1 41.693,40.623 42.723,41.652 42.723,43.205 43.725,44.208 U2.5
OSCOUT: C8.1 U2.6 X1.3 | length 5.2
  Top Layer w0.254: U2.6 44.225,42.805 X1.3 44.034,42.133 C8.1
OUTB: C30.1 R23.1 U2.14 U4.7 | length 20.7
  Top Layer w0.254: U2.14 48.534,47.17 49.528,47.17 50.046,46.652 50.046,45.042 v1(49.479,44.475)
  Top Layer w0.508: U4.7 45.147,37.044 46.025,37.922 v1(47.904,37.922) 49.135,37.922 C30.1@49.147,37.935 ; R23.1 C30.1
  Bottom Layer w0.254: v1(47.904,37.922) 48.438,38.456 48.438,43.434 v1(49.479,44.475)
OUTC: C33.1 R36.1 U2.15 U4.8 | length 24.5
  Top Layer w0.254: U2.15 49.806,47.678 50.089,47.396 50.749,46.736 50.749,44.532 50.409,44.191 49.652,43.434 v1(49.555,43.434)
  Top Layer w0.508: U4.8 40.359,33.807 40.363,33.811 R36.1 40.366,36.469 42.109,36.469 42.258,36.619 42.408,36.619 42.975,37.186 v1(43.002,37.186)
  Bottom Layer w0.254: v1(43.002,37.186) 48.514,37.186 49.53,38.202 49.53,43.409 v1(49.555,43.434)
OUTD: C42.1 R49.1 U2.16 U4.14 | length 44.3
  Top Layer w0.254: C42.1 41.187,21.615 50.648,21.615 52.273,23.241 52.273,39.141 v1(51.562,39.853) ; U2.16 50.272,48.178 51.587,46.863 v1(51.587,43.688)
  Top Layer w0.508: U4.14 40.201,26.133 R49.1 40.201,22.615 C42.1
  Bottom Layer w0.254: v1(51.562,39.853) 51.575,39.865 51.575,43.675 v1(51.587,43.688)
PA9_TX: P1.5 U2.30 | length 17.3
  Top Layer w0.254: v1(44.247,56.286) 44.247,56.274 44.725,55.795 U2.30
  Bottom Layer w0.254: v1(44.247,56.286) 44.247,60.554 P1.5
PA10_RX: P1.3 U2.31 | length 16.5
  Top Layer w0.254: v1(43.612,55.601) 44.225,54.987 U2.31
  Bottom Layer w0.254: v1(43.612,55.601) 43.586,55.626 43.586,62.432 P1.3
PWM_A: U2.10 U6.2 | length 23.1
  Top Layer w0.254: U2.10 46.225,43.64 48.59,41.275 52.045,41.275 52.832,40.488 52.832,29.134 53.924,28.042 U6.2
PWM_B: U2.11 U7.2 | length 10
  Top Layer w0.254: U2.11 46.725,43.876 48.56,42.042 U7.2
PWM_C: U2.12 U9.2 | length 21.4
  Top Layer w0.254: U2.12 47.225,44.265 48.819,42.672 51.664,42.672 52.68,43.688 52.68,55.499 53.222,56.042 U9.2
RESET: C1.1 R3.2 SW1.2 U2.7 | length 41.2
  Top Layer w0.254: U2.7 44.725,50.466 v1(45.466,51.206) ; v1(47.86,55.423) 47.879,55.441 47.879,58.852 48.895,59.868 51.359,59.868 51.638,60.147 51.638,64.313 52.273,64.948 v1(54.762,64.948) ; v1(57.683,66.675) 57.683,69.088 58.522,69.926 SW1.2 ; v1(60.173,66.65) 60.198,66.624 61.598,66.624 ; R3.2@61.606,65.667 C1.1
  Bottom Layer w0.254: v1(45.466,51.206) 47.86,53.601 v1(47.86,55.423) ; v1(54.762,64.948) 56.109,66.294 57.302,66.294 v1(57.683,66.675) 60.147,66.675 v1(60.173,66.65)
RST_IPS: IPS1.6 U2.27 | length 29.7
  Top Layer w0.254: v1(24.536,62.078) 27.508,59.106 44.526,59.106 46.225,57.407 U2.27
  Bottom Layer w0.254: IPS1.6 22.43,62.079 24.535,62.079 v1(24.536,62.078)
SCL: U1.2 U2.21 | length 47.7
  Top Layer w0.254: U2.21 48.534,50.687 49.317,50.687 49.328,50.698 50.266,50.698 52.197,52.629 52.197,56.896 54.762,59.461 v1(54.762,60.681) ; v1(57.658,62.467) 58.158,62.967 83.16,62.967 84.14,63.947 U1.2
  Bottom Layer w0.254: v1(54.762,60.681) 56.549,62.467 v1(57.658,62.467)
SDA: U1.3 U2.22 | length 46
  Top Layer w0.254: U2.22 48.534,51.187 49.943,51.187 51.689,52.934 51.689,57.379 53.95,59.639 53.95,60.964 54.732,61.746 v1@54.762,61.746 ; v1(57.658,63.602) 81.966,63.602 82.89,64.526 U1.3
  Bottom Layer w0.254: v1(54.762,61.747) 56.617,63.602 v1(57.658,63.602)
SPI1_MOSI: IPS1.3 U2.28 | length 27.9
  Top Layer w0.254: v1(28.397,58.141) 44.399,58.141 45.725,56.814 U2.28
  Bottom Layer w0.254: IPS1.3 24.347,59.981 26.187,58.141 v1(28.397,58.141)
SPI1_NSS: IPS1.7 U2.25 | length 31.7
  Top Layer w0.254: v1(25.112,62.781) 27.466,60.427 45.466,60.427 47.225,58.667 U2.25
  Bottom Layer w0.254: IPS1.7 v1(25.112,62.781)
SPI1_SCK: IPS1.4 U2.26 | length 29.9
  Top Layer w0.254: v1(28.169,59.792) 44.933,59.792 46.725,57.999 U2.26
  Bottom Layer w0.254: IPS1.4 24.867,60.681 25.756,59.792 v1(28.169,59.792)
SWCLK: P1.6 U2.37 | length 38.9
  Top Layer w0.254: v1(39.624,56.261) 36.551,56.261 35.839,55.55 35.839,51.867 36.474,51.232 37.871,51.232 38.818,52.178 U2.37
  Bottom Layer w0.254: v1(39.624,56.261) 40.31,56.947 40.31,69.367 42.487,71.544 49.919,71.544 P1.6
SWIO: P1.4 U2.34 | length 22
  Top Layer w0.254: v1(42.139,56.49) 42.139,55.316 42.725,54.729 U2.34
  Bottom Layer w0.254: v1(42.139,56.49) 42.139,67.437 43.651,68.949 47.562,68.949 P1.4
pads on no net: H1.11 H2.11 IPS1.1 IPS1.2 IPS1.9 P1.7 P1.8 S1.3 U1.5 U1.6 U2.2 U2.3 U2.4 U2.13 U2.18 U2.19 U2.32 U2.33 U2.38 U2.39 U2.40 U2.42 U2.43 U2.45 U2.46

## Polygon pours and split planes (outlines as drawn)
IB+ on Top Layer "NONET_L-01_P-001" (solid, pour order 0): 82.831,37.12 83.009,36.942 88.877,36.942 89.207,37.272 89.207,45.07 89.088,45.188 82.924,45.188 82.831,45.095
IC+ on Top Layer "NONET_L-01_P-001" (solid, pour order 3): 82.831,51.12 83.009,50.942 88.877,50.942 89.207,51.272 89.207,59.07 89.088,59.188 82.924,59.188 82.831,59.095
IA+ on Top Layer "NONET_L-01_P-001" (solid, pour order 4): 82.831,23.12 83.009,22.942 88.877,22.942 89.207,23.272 89.207,31.07 89.088,31.188 82.924,31.188 82.831,31.095
GND on Top Layer "NONET_L-01_P-001" (solid, pour order 7): 20.975,51.866 34.056,51.866 34.137,51.947 34.137,53.614 34.043,53.708 20.963,53.708 20.874,53.619 20.874,51.968
GND on Top Layer "NONET_L-01_P-001" (solid, pour order 9): 20.98,42.837 33.921,42.837 33.985,42.901 33.985,43.713 33.964,43.735 29.468,43.735 29.21,43.993 29.21,44.475 29.007,44.679 20.968,44.679 20.879,44.589 20.879,42.938
GND on Top Layer "NONET_L-01_P-001" (solid, pour order 10): 11.836,47.707 12.141,48.012 12.141,49.073 12.268,49.2 16.434,49.2 16.485,49.149 16.485,47.574 16.358,47.447 12.675,47.447 12.421,47.193 12.421,45.822 12.37,45.771 11.887,45.771 11.836,45.822
NetC9_2 on Top Layer "NONET_L-01_P-001" (solid, pour order 11): 16.84,49.21 16.599,49.451 12.804,49.451 12.268,49.987 12.548,50.267 19.101,50.267 19.329,50.038 19.329,45.618 19.228,45.517 16.891,45.517 16.84,45.568
NetC7_2 on Top Layer "NONET_L-01_P-001" (solid, pour order 12): 12.852,41.808 19.329,41.808 19.38,41.859 19.38,44.729 19.253,44.856 12.852,44.856 12.802,44.806 12.802,41.859
NetC9_2 on Top Layer "NONET_L-01_P-001" (solid, pour order 13): 12.192,51.46 12.192,53.137 12.471,53.416 15.367,53.416 15.596,53.188 15.596,50.546 15.977,50.165 15.682,49.871 12.922,49.871
GND on Top Layer "NONET_L-01_P-001" (solid, pour order 14): 90.856,61.874 88.773,63.957 88.773,71.857 89.103,72.187 97.636,72.187 cw(c97.636,71.17) 98.654,71.17 98.654,21.947 cw(c97.636,21.947) 97.636,20.93 91.542,20.93 90.856,21.615
B on Top Layer "NONET_L-01_P-001" (solid, pour order 22): 72.085,45.211 71.958,45.211 71.958,45.161 71.958,42.062 72.085,41.935 76.987,41.935 77.241,41.681 77.673,41.681 78.384,42.393 78.384,45.211
A on Top Layer "NONET_L-01_P-001" (solid, pour order 23): 72.085,31.211 71.958,31.211 71.958,31.161 71.958,28.062 72.085,27.935 76.987,27.935 77.241,27.681 77.673,27.681 78.384,28.393 78.384,31.211
C on Top Layer "NONET_L-01_P-001" (solid, pour order 24): 72.085,59.211 71.958,59.211 71.958,59.161 71.958,56.062 72.085,55.935 76.987,55.935 77.241,55.681 77.673,55.681 78.384,56.393 78.384,59.211
B on Top Layer "NONET_L-01_P-001" (solid, pour order 27): 77.884,46.126 77.884,45.916 78.003,45.796 78.003,45.314 77.876,45.187 78.08,44.983 78.283,44.983 78.283,45.294 78.611,45.623 78.232,46.002 78.232,46.05
A on Top Layer "NONET_L-01_P-001" (solid, pour order 28): 77.884,32.126 77.884,31.916 78.003,31.796 78.003,31.314 77.876,31.187 78.08,30.983 78.283,30.983 78.283,31.294 78.611,31.623 78.232,32.002 78.232,32.05
C on Top Layer "NONET_L-01_P-001" (solid, pour order 29): 77.884,60.126 77.884,59.916 78.003,59.796 78.003,59.314 77.876,59.187 78.08,58.983 78.283,58.983 78.283,59.294 78.611,59.623 78.232,60.002 78.232,60.05
NetC19_1 on Top Layer "NONET_L-01_P-001" (solid, pour order 34): 10.39,20.93 28.016,20.93 29.083,21.996 29.083,31.521 28.702,31.902 10.414,31.902 9.373,30.861 9.373,21.947 ccw(c10.39,21.947)
GND on Top Layer "NONET_L-01_P-001" (solid, pour order 35): 10.871,33.02 28.448,33.02 28.981,33.553 28.981,37.541 28.499,38.024 11.557,38.024 10.617,37.084
GND on Top Layer "NONET_L-01_P-001" (solid, pour order 37): 15.795,33.837 11.185,38.446 11.185,42.739 10.943,42.981 10.537,42.981 10.389,43.129 10.389,44.475 10.693,44.78 12.217,44.78 12.421,44.983 12.421,45.822 11.836,45.822 11.659,45.644 9.576,45.644 9.373,45.441 9.373,33.884 10.236,33.02 13.501,33.02
5V on Top Layer "NONET_L-01_P-001" (solid, pour order 38): 56.388,68.682 55.372,67.666 55.372,65.684 56.388,64.668
5V on Top Layer "NONET_L-01_P-001" (solid, pour order 39): 54.686,66.192 56.109,67.615 56.388,67.615 56.388,66.243 56.083,65.938
12V on Bottom Layer "NONET_L-01_P-001" (solid, pour order 5): 28.727,20.93 70.917,20.93 71.831,21.844 71.831,60.63 71.501,60.96 66.421,60.96 66.167,60.706 66.167,25.908 64.846,24.587 37.033,24.587 36.525,25.095 36.525,26.264 36.22,26.568 28.524,26.568 28.016,26.06 28.016,21.641 ccw(c28.727,21.641)
GND on Bottom Layer "NONET_L-01_P-001" (solid, pour order 16): 10.39,20.93 27.254,20.93 27.407,21.082 27.407,28.346 28.143,29.083 34.9,29.083 35.535,28.448 50.241,28.448 50.571,28.778 50.571,34.29 50.241,34.62 9.373,34.62 9.373,21.947 ccw(c10.39,21.947)
GND on Bottom Layer "NONET_L-01_P-001" (solid, pour order 17): 36.202,33.292 34.62,34.874 34.62,37.465 34.95,37.795 46.736,37.795 47.777,38.837 47.777,44.374 49.327,45.923 56.566,45.923 57.531,44.958 57.531,26.746 57.048,26.264 55.296,26.264 55.016,25.984 55.016,25.298 55.448,24.867 64.643,24.867 65.862,26.086 65.862,72.187 10.389,72.187 ccw(c10.389,71.171) 9.373,71.171 9.373,33.61
B on Bottom Layer "NONET_L-01_P-001" (solid, pour order 19): 78.232,46.05 78.232,42.316 78.486,42.062 98.654,42.062 98.654,46.355 78.537,46.355
A on Bottom Layer "NONET_L-01_P-001" (solid, pour order 20): 78.537,28.067 91.872,28.067 92.202,28.397 92.202,37.084 92.507,37.389 98.171,37.389 98.654,37.871 98.654,41.478 98.247,41.885 89.027,41.885 88.773,41.631 88.773,32.766 88.341,32.334 78.537,32.334 78.232,32.029 78.232,28.372
C on Bottom Layer "NONET_L-01_P-001" (solid, pour order 30): 78.537,60.325 91.872,60.325 92.202,59.995 92.202,51.156 92.735,50.622 98.261,50.622 98.654,50.229 98.654,46.888 98.273,46.507 89.027,46.507 88.773,46.761 88.773,55.626 88.341,56.058 78.537,56.058 78.232,56.363 78.232,60.02
GND on Bottom Layer "NONET_L-01_P-001" (solid, pour order 32): 65.761,60.909 66.167,61.316 71.78,61.316 72.314,60.782 72.314,21.006 72.39,20.93 97.636,20.93 ccw(c97.636,21.947) 98.654,21.947 98.654,36.678 98.298,37.033 93.015,37.033 92.608,36.627 92.608,28.016 92.024,27.432 77.923,27.432 77.673,27.681 77.673,32.131 78.461,32.918 87.605,32.918 88.24,33.553 88.24,41.199 87.681,41.758 78.156,41.758 77.749,42.164 77.749,46.482 78.283,47.015 87.757,47.015 88.316,47.574 88.316,55.093 87.808,55.601 78.465,55.601 77.927,56.139 77.927,60.198 78.461,60.731 91.973,60.731 92.558,60.147 92.558,51.333 93.015,50.876 98.349,50.876 98.654,51.181 98.654,71.17 ccw(c97.636,71.17) 97.636,72.187 65.862,72.187
GND on Bottom Layer "NONET_L-01_P-001" (solid, pour order 36): 54.661,25.273 55.067,25.679 56.159,25.679
no net on Top Solder "NONET_L-01_P-001" (solid): 74.242,29.566 75.667,29.566 75.667,27.932 75.667,27.931 74.242,27.931
no net on Top Solder "NONET_L-01_P-001" (solid): 74.242,43.566 75.667,43.566 75.667,41.932 75.667,41.931 74.242,41.931
no net on Top Solder "NONET_L-01_P-001" (solid): 74.242,57.566 75.667,57.566 75.667,55.932 75.667,55.931 74.242,55.931

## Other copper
Top Layer:
  pour cut-out: 92.735,50.597 93.167,51.029 98.146,51.029 98.654,51.537 98.654,36.678 98.298,37.033 93.294,37.033 92.735,37.592
Bottom Layer:
  pour cut-out: 58.166,67.012 53.289,67.012 53.289,61.036 53.696,60.63 57.76,60.63 58.166,61.036
  pour cut-out: 58.166,65.42 59.116,66.37 58.395,66.37 58.166,66.599

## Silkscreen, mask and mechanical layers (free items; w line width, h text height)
Top Overlay:
  lines w0.254: 44.909,64.465 57.758,64.465 ; 47.57,63.043 47.57,65.788 ; 50.084,63.017 50.084,65.814 ; 52.421,63.017 52.421,65.788 ; 55.143,63.043 55.143,65.862 ; 44.909,63.017 57.758,63.017 57.758,65.862 44.909,65.862 44.909,63.017
  text "3.3V" at 52.984,64.936 h0.91
  text "5.0V" at 55.637,64.936 h0.91
  text "GND" at 45.42,64.929 h0.91
  text "DIO" at 48.076,64.929 h0.91
  text "CLK" at 50.409,64.929 h0.91
  text "GND" at 79.217,64.655 h1.02
  text "SDA" at 81.496,64.655 h1.02
  text "SCL" at 83.755,64.655 h1.02
  text "5V" at 86.258,64.655 h1.02
  text "RES" at 61.505,63.587 h0.91
  text "RX1" at 48.069,63.388 h0.91
  text "TX1" at 50.546,63.388 h0.91
  text "3.3V" at 52.871,63.388 h0.91
  text "5.0V" at 55.637,63.388 h0.91
  text "GND" at 45.42,63.38 h0.91
  text "Foc-Learning-Board By:LPBOSS" at 52.447,21.412 h1.52
Top Solder:
  lines w0.254: 93.777,27.522 93.777,30.926 93.777,36.107 ; 93.777,52.095 93.777,64.872 ; 94.634,27.522 94.634,30.926 94.634,36.107 ; 94.634,52.095 94.634,64.872 ; 95.491,27.522 95.491,30.926 95.491,36.107 ; 95.491,52.095 95.491,64.872 ; 96.349,27.522 96.349,30.926 96.349,36.107 ; 96.349,52.095 96.349,64.872 ; 97.206,27.522 97.206,30.926 97.206,36.107 ; 97.206,52.095 97.206,64.872
Mechanical 1:
  lines w0.254: 10.39,72.085 97.638,72.085 cw(c97.638,71.068) 98.655,71.068 ; 10.39,72.086 ccw(c10.39,71.069) 9.373,71.069 9.373,22.226 ccw(c10.39,22.226) 10.39,21.209 97.636,21.209 ccw(c97.636,22.226) 98.654,22.226 98.654,71.068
